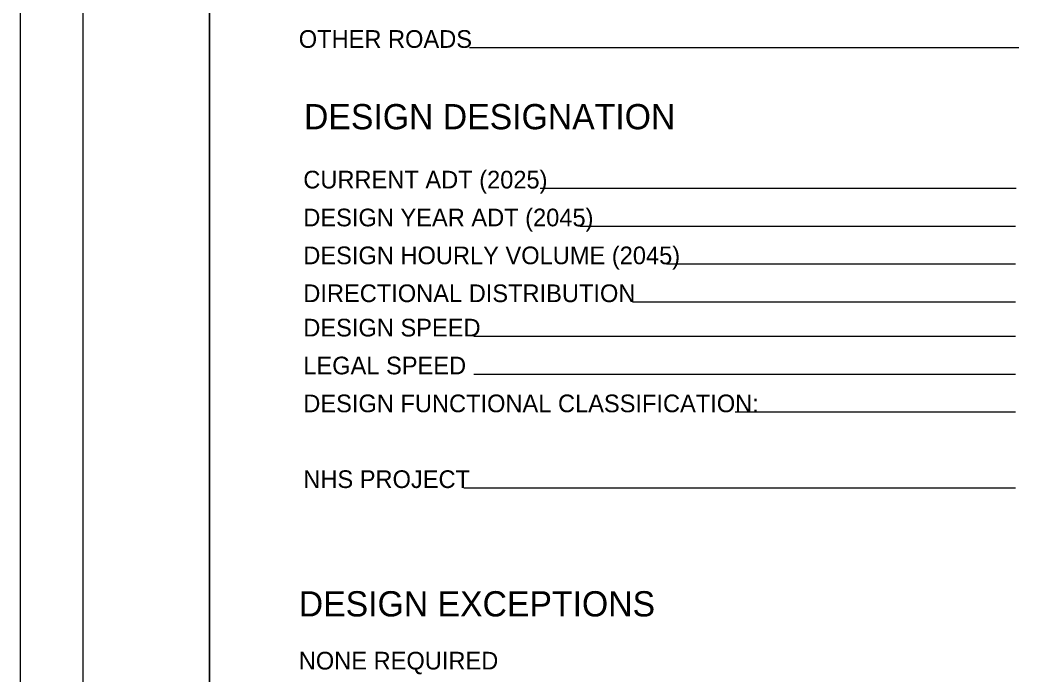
# Model space of a CAD drawing. Extents: x 0 to 34, y 0 to 22.
# Drawn here: x 0 to 7.94, y 5.91 to 11.1 of the extents above; entities that cross this region are included whole.
import ezdxf

# ---------------------------------------------------------------- set-up
doc = ezdxf.new("R2010")
doc.units = 0
for name, color, linetype in [('Default', 7, 'Continuous'), ('SH_Border', 7, 'Continuous'), ('SH_Cut_Line', 7, 'Continuous'), ('SH_Data', 7, 'Continuous'), ('SH_Text', 7, 'Continuous')]:
    doc.layers.add(name, color=color, linetype=linetype)

msp = doc.modelspace()

# ---------------------------------------------------------------- linework, layer by layer
at = {"layer": 'SH_Border'}
for points in [[(0.5, 21.5), (1.5, 21.5), (1.5, 0.5), (0.5, 0.5)], [(1.5, 21.5), (33.5, 21.5), (33.5, 0.5), (1.5, 0.5)]]:
    msp.add_lwpolyline(points, close=True, dxfattribs=at)
at = {"layer": 'SH_Cut_Line'}
msp.add_lwpolyline([(0, 0), (34, 0), (34, 22), (0, 22)], close=True, dxfattribs=at)
at = {"layer": 'SH_Data'}
for p, q in [((7.9142, 10.8762), (3.5613, 10.8762)), ((7.8926, 9.7629), (4.1213, 9.7629)), ((7.8871, 9.4629), (4.4387, 9.4629)), ((7.8871, 9.1629), (5.1225, 9.1629)), ((7.8871, 8.8629), (4.8539, 8.8629)), ((7.8871, 8.5909), (3.5962, 8.5909)), ((7.8871, 8.2909), (3.5962, 8.2909)), ((7.8871, 7.9909), (5.6668, 7.9909)), ((7.8871, 7.3909), (3.5171, 7.3909))]:
    msp.add_line(p, q, dxfattribs=at)

# ---------------------------------------------------------------- texts
at = {"layer": 'Default'}
msp.add_text('NONE REQUIRED', height=0.14, dxfattribs=at).set_placement((2.2086, 5.9539))
at = {"layer": 'SH_Data'}
msp.add_text('DESIGN DESIGNATION', height=0.2, dxfattribs=at).set_placement((2.2502, 10.2313))
at = {"layer": 'SH_Text'}
for s, height, p in [('OTHER ROADS', 0.14, (2.2086, 10.8762)), ('CURRENT ADT (2025)', 0.14, (2.2446, 9.7629)), ('DESIGN YEAR ADT (2045)', 0.14, (2.2446, 9.4629)), ('DESIGN HOURLY VOLUME (2045)', 0.14, (2.2446, 9.1629)), ('DIRECTIONAL DISTRIBUTION', 0.14, (2.2446, 8.8629)), ('DESIGN SPEED', 0.14, (2.2446, 8.5909)), ('LEGAL SPEED', 0.14, (2.2446, 8.2909)), ('DESIGN FUNCTIONAL CLASSIFICATION:', 0.14, (2.2446, 7.9909)), ('NHS PROJECT', 0.14, (2.2446, 7.3909)), ('DESIGN EXCEPTIONS', 0.2, (2.2086, 6.3739))]:
    msp.add_text(s, height=height, dxfattribs=at).set_placement(p)

doc.saveas('drawing.dxf')
